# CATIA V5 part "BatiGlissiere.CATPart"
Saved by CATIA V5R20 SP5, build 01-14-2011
Part number: BatiGlissiere
Bounding box of the stored display mesh (mm): x -42 to 75, y -230 to 230, z -350 to 230
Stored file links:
  C:\Documents and Settings\ndumont\Bureau\ndumont_CAO\BatiGlissiere.CATPart
  C:\Documents and Settings\ndumont\Bureau\ndumont_CAO\ndumont.CATProduct
  J:\Rendus\Rendu_IAO\ndumont_CAO\SqueletteBarreDC.CATPart
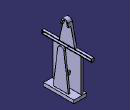
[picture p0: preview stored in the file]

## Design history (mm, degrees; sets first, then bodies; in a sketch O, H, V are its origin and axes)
Parameters
  AngleButee = 25 deg
External parameters (linked from other documents)
  External.EpaisseurCoulisseau = 20 mm
  External.DiametreTrousABetDC = 18 mm
  External.EpaisseurABetDC = 20 mm
  External.DiametrePivotABetDC = 40 mm
  External.LongueurDC = 200 mm
Set1
  Line1 to Line8: linked copy from another document
  Plane1: linked copy from another document
  Point1: linked copy from another document
  Point2: linked copy from another document
Set2
  MultiExtract1: ListOfMultiExtractConstraints (MultiExtractConstraint face of Pad1 from Sketch1.L1; MultiExtractConstraint face of Pad1 from Sketch1.L2; MultiExtractConstraint face of Pad1 from Sketch1.L8; MultiExtractConstraint face of Pad1 from Sketch1.L3; MultiExtractConstraint face of Pad1 from Sketch1.L6; MultiExtractConstraint start face of Pad1; MultiExtractConstraint end face of Pad1; MultiExtractConstraint face of Pad1 from Sketch1.L4)
  Point3: type OnCurve, Support edge of MultiExtract1, Ratio 0.5
  Point4: type OnCurve, Support edge of MultiExtract1, Ratio 0.5
  Point5: type OnCurve, Support edge of MultiExtract1, Ratio 0.5
  Point6: type OnCurve, Support edge of MultiExtract1, Ratio 0.5
  Line9: type PtPt, FirstPoint vertex [face of Pad1 from Sketch1.L6 | end face of Pad1 | face of Pad1 from Sketch1.L5], SecondPoint Point5
  Line10: type PtPt, FirstPoint Point5, SecondPoint Point6
  Line11: type PtPt, FirstPoint Point6, SecondPoint vertex [start face of Pad1 | face of Pad1 from Sketch1.L6]
  Line12: type PtPt, FirstPoint vertex [start face of Pad1 | face of Pad1 from Sketch1.L6], SecondPoint Point4
  Line13: type PtPt, FirstPoint Point4, SecondPoint Point3
  Line14: type PtPt, FirstPoint Point3, SecondPoint vertex [face of Pad1 from Sketch1.L7 | end face of Pad1 | face of Pad1 from Sketch1.L6]
  Line15: type PtPt, FirstPoint Point5, SecondPoint vertex [face of Pad1 from Sketch1.L8 | end face of Pad1 | face of Pad1 from Sketch1.L5]
  Line16: type PtPt, FirstPoint Point6, SecondPoint vertex [face of Pad1 from Sketch1.L8 | start face of Pad1 | face of Pad1 from Sketch1.L5]
  Line17: type PtPt, FirstPoint Point3, SecondPoint vertex [face of Pad1 from Sketch1.L8 | end face of Pad1 | face of Pad1 from Sketch1.L7]
  Line18: type PtPt, FirstPoint Point4, SecondPoint vertex [face of Pad1 from Sketch1.L8 | start face of Pad1 | face of Pad1 from Sketch1.L7]
  Fill1: Boundary (Line9; Line10; Line11; edge of MultiExtract1)
  Fill2: Boundary (Line10; Line15; edge of MultiExtract1; Line16)
  Fill3: Boundary (edge of MultiExtract1; Line17; Line13; Line18)
  Fill4: Boundary (Line13; Line14; edge of MultiExtract1; Line12)
  Join1: Elements (MultiExtract1; Fill4; Fill3; Fill1; Fill2)
Body1 (main body)
  Sketch1 on yz-plane, origin (0, 0, 0), H (0, 1, 0), V (0, 0, 1)
    line L1 (-230, 15) -> (230, 15)
    line L2 (230, 15) -> (230, -15)
    line L3 (230, -15) -> (-230, -15)
    line L4 (-230, -15) -> (-230, 15)
    line L5 (-225, 10) -> (225, 10)
    line L6 (225, 10) -> (225, -10)
    line L7 (225, -10) -> (-225, -10)
    line L8 (-225, -10) -> (-225, 10)
    reference projected line E1 (210, 15) -> (-210, 15) from Line1
    reference projected line E2 (230, -15) -> (230, 15) from Line2
    reference projected line E3 (-210, -15) -> (210, -15) from Line3
    reference projected line E4 (-230, 15) -> (-230, -15) from Line4
    reference projected line E5 (205, 10) -> (-205, 10) from Line5
    reference projected line E6 (225, -10) -> (225, 10) from Line6
    reference projected line E7 (-205, -10) -> (205, -10) from Line7
    reference projected line E8 (-225, 10) -> (-225, -10) from Line8
    horizontal: L1 H, L3 H, L5 H, L7 H
    vertical: L2 V, L4 V, L6 V, L8 V
    coincidence: L1 E1, L2 E2, L3 E3, L4 E4, L5 E5, L6 E6, L7 E7, L8 E8
  Pad1: profile Sketch1, direction (-1, 0, 0), length 22 {= External.EpaisseurCoulisseau +2mm}
  Sketch2 on Plane1, origin (30, 0, 0), H (0, 1, 0), V (0, 0, 1)
    circle A1 centre (0, 0) radius 9
    reference projected point E1 (0, 0) from Point1
    radius A1 = 9 {= External.DiametreTrousABetDC /2}
    concentricity: A1 E1
  Pad2: profile Sketch2, direction (1, 0, 0), length 10 {= External.EpaisseurABetDC /2}, mirrored extent
  Sketch3 on end face of Pad2, origin (40, 0, 0), H (0, 1, 0), V (0, 0, 1)
    arc A1 centre (0, 0) radius 28 from (27.7605, 3.6547) to (-27.7605, 3.6547) ccw
    reference projected point E1 (0, 0) from Point1
    line L1 (-27.7605, 3.6547) -> (-70.3704, -320)
    point P3 (-70.3704, -320)
    line L2 (-70.3704, -320) -> (70.3704, -320)
    point P4 (70.3704, -320)
    line L3 (70.3704, -320) -> (27.7605, 3.6547)
    reference projected point E2 (0, 0) from Point1
    radius A1 = 28 {= 0.7*External.DiametrePivotABetDC}
    angle L3 L1 = 15
    distance E2 L2 = 320 {= External.LongueurDC +(External.DiametrePivotABetDC /2)+100mm}
    concentricity: A1 E1
    horizontal: L2 H
    tangency: L3 A1, L1 A1
    symmetry: P4 P3 V
  Pad3: profile Sketch3, direction (1, 0, 0), length 15
  Sketch4 on face of Pad3 from Sketch3.L2, origin (0, 0, -320), H (1, 0, 0), V (0, -1, 0)
    line L1 (-42, 140.3704) -> (75, 140.3704)
    line L2 (75, 140.3704) -> (75, -140.3704)
    line L3 (75, -140.3704) -> (-42, -140.3704)
    line L4 (-42, -140.3704) -> (-42, 140.3704)
    reference projected line E1 (40, 70.3704) -> (55, 70.3704) from edge [face of Pad3 from Sketch3.L2 | face of Pad3 from Sketch3.L1]
    reference projected line E2 (55, 70.3704) -> (55, -70.3704) from edge [face of Pad3 from Sketch3.L2 | end face of Pad3]
    reference projected line E3 (-22, 210) -> (-22, -210) from edge [end face of Pad1 | face of Pad1 from Sketch1.L3]
    distance E1 L1 = 70
    distance L2 E2 = 20
    distance E3 L4 = 20
    horizontal: L1 H, L3 H
    vertical: L2 V, L4 V
    symmetry: L1 L3 H
  Pad4: profile Sketch4, direction (0, 0, -1), length 30
  Sketch5 on face of Pad1 from Sketch1.L3, origin (0, 0, -15), H (1, 0, 0), V (0, -1, 0)
    line L1 (-21, 130.3704) -> (-1, 130.3704)
    line L2 (-1, 130.3704) -> (-1, -130.3704)
    line L3 (-1, -130.3704) -> (-21, -130.3704)
    line L4 (-21, -130.3704) -> (-21, 130.3704)
    reference projected line E1 (75, 140.3704) -> (-45, 140.3704) from edge [face of Pad4 from Sketch4.L1 | end face of Pad4]
    reference projected line E2 (-45, -140.3704) -> (75, -140.3704) from edge [face of Pad4 from Sketch4.L3 | end face of Pad4]
    reference projected line E3 (-22, 230) -> (-22, -230) from edge [end face of Pad1 | face of Pad1 from Sketch1.L3]
    distance L1 E1 = 10
    distance L3 E2 = 10 {= Sketch5.distance(L1 E1)}
    distance L4 L2 = 20
    distance L4 E3 = 1
    horizontal: L1 H, L3 H
    vertical: L2 V, L4 V
  Pad5: profile Sketch5, direction (0, 0, -1), up to the existing solid (limit type 2)
  Sketch6 on face of Pad5 from Sketch5.L4, origin (-21, 0, 0), H (0, -1, 0), V (0, 0, 1)
    arc A1 centre (0, 200) radius 30 from (29.2889, 206.4932) to (-29.2889, 206.4932) ccw
    point P1 (0, 200)
    line L1 (-29.2889, 206.4932) -> (-71.7419, 15)
    line L2 (71.7419, 15) -> (29.2889, 206.4932)
    line L3 (-71.7419, 15) -> (71.7419, 15)
    reference projected line E1 (-210, 15) -> (210, 15) from edge [end face of Pad1 | face of Pad1 from Sketch1.L1]
    radius A1 = 30 {= (External.DiametrePivotABetDC /2)+10mm}
    angle L2 L1 = 25 {= AngleButee}
    distance P1 H = 200 {= External.LongueurDC}
    symmetry: L2 L1 V
    tangency: L2 A1, L1 A1
    coincidence: L3 E1
  Pad6: profile Sketch6, direction (1, 0, 0), length 20
  Sketch7 on yz-plane, origin (0, 0, 0), H (0, 1, 0), V (0, 0, 1)
    arc A1 centre (0, 200) radius 20 from (19.5259, 204.3288) to (-19.5259, 204.3288) ccw
    line L1 (29.2889, 206.4932) -> (35.7821, 177.2043)
    line L2 (35.7821, 177.2043) -> (26.0191, 175.0399)
    line L3 (-19.5259, 204.3288) -> (-26.0191, 175.0399)
    line L4 (-26.0191, 175.0399) -> (-35.7821, 177.2043)
    line L5 (26.0191, 175.0399) -> (19.5259, 204.3288)
    arc A2 centre (0, 200) radius 30 from (29.2889, 206.4932) to (-29.2889, 206.4932) ccw
    line L6 (-35.7821, 177.2043) -> (-29.2889, 206.4932)
    reference projected arc E1 centre (0, 200) radius 30 from (29.2889, 206.4932) to (-29.2889, 206.4932) ccw from edge [face of Pad6 from Sketch6.A1 | end face of Pad6]
    radius A1 = 20 {= External.DiametrePivotABetDC /2}
    angle L5 L3 = 25 {= AngleButee}
    radius A2 = 30 {= Sketch7.radius(A1) +10mm}
    length L3 = 30
    length L5 = 30 {= Sketch7.length(L3)}
    perpendicularity: L2 L1, L4 L3
    symmetry: L5 L3 V
    tangency: L5 A1, L3 A1, L1 A2, L6 A2
    concentricity: A2 A1, A2, A2 E1
    parallelism: L1 L5, L3 L6
  Pad7: profile Sketch7, direction (1, 0, 0), length 20 {= External.EpaisseurABetDC}, opposite side up to the existing solid (limit type 2)
  Sketch8 on yz-plane, origin (0, 0, 0), H (0, 1, 0), V (0, 0, 1)
    arc A1 centre (0, -200) radius 20 from (-19.5259, -204.3288) to (19.5259, -204.3288) ccw
    line L1 (29.2889, -206.4932) -> (35.7821, -177.2043)
    line L2 (35.7821, -177.2043) -> (26.0191, -175.0399)
    line L3 (-19.5259, -204.3288) -> (-26.0191, -175.0399)
    line L4 (-26.0191, -175.0399) -> (-35.7821, -177.2043)
    line L5 (26.0191, -175.0399) -> (19.5259, -204.3288)
    arc A2 centre (0, -200) radius 30 from (-29.2889, -206.4932) to (29.2889, -206.4932) ccw
    line L6 (-35.7821, -177.2043) -> (-29.2889, -206.4932)
    point P10 (0, -200)
    radius A1 = 20 {= External.DiametrePivotABetDC /2}
    radius A2 = 30 {= Sketch8.radius(A1) +10mm}
    length L5 = 30 {= Sketch8.length(L3)}
    length L3 = 30
    angle L5 L3 = 25 {= AngleButee}
    distance H P10 = 200 {= External.LongueurDC}
    perpendicularity: L2 L1, L4 L3
    symmetry: L5 L3 V
    tangency: L5 A1, L3 A1, L1 A2, L6 A2
    concentricity: A2 A1
    parallelism: L1 L5, L3 L6
  Pad8: profile Sketch8, direction (1, 0, 0), length 20 {= External.EpaisseurABetDC}, opposite side up to the existing solid (limit type 2)
  CloseSurface1: CloseElement Join1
